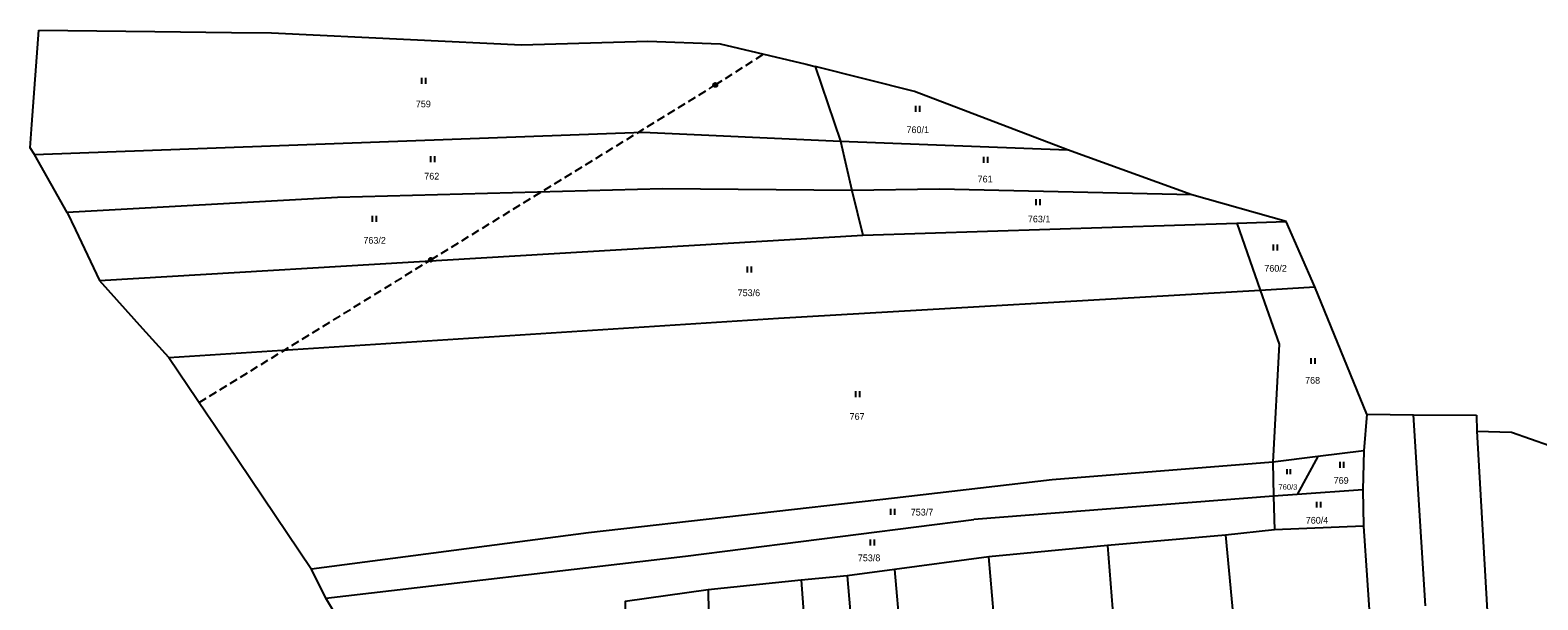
# Model space of a CAD drawing. Extents: x -820420 to -815896, y -1105820 to -1103643.
# Drawn here: x -817269.2 to -816887.9, y -1103786.7 to -1103642.6 of the extents above; entities that cross this region are included whole.
import ezdxf
from ezdxf.enums import TextEntityAlignment as Align

# ---------------------------------------------------------------- set-up
doc = ezdxf.new("R2010")
doc.units = 0
doc.header["$LTSCALE"] = 0.68
doc.linetypes.add('MEDIUM_DASHED', pattern=[4.5, 3, -1.5])
for name, color, linetype, lineweight in [('1', 7, 'Continuous', 25), ('3', 7, 'Continuous', 25), ('6', 7, 'Continuous', 25)]:
    doc.layers.add(name, color=color, linetype=linetype, lineweight=lineweight)
doc.layers.add('2', color=7, linetype='Continuous')

msp = doc.modelspace()

# ---------------------------------------------------------------- linework, layer by layer
at = {"layer": '1'}
for p, q in [((-817268.77, -1103666.4), (-817267.03, -1103642.55)), ((-817267.03, -1103642.55), (-817237.71, -1103642.9)), ((-817237.71, -1103642.9), (-817218.32, -1103643.13)), ((-817218.32, -1103643.13), (-817208.15, -1103643.25)), ((-817208.15, -1103643.25), (-817172.99, -1103644.95)), ((-817172.99, -1103644.95), (-817144.98, -1103646.31)), ((-817144.98, -1103646.31), (-817112.98, -1103645.35)), ((-817112.98, -1103645.35), (-817094.67, -1103645.99)), ((-817094.67, -1103645.99), (-817072.98, -1103651.16)), ((-817072.98, -1103651.16), (-817070.65, -1103651.72)), ((-817070.65, -1103651.72), (-817064.29, -1103670.68)), ((-817045.6, -1103658.05), (-817070.65, -1103651.72)), ((-817006.88, -1103672.86), (-817045.6, -1103658.05)), ((-817269.2, -1103672.33), (-817268.77, -1103666.4)), ((-817268.07, -1103673.99), (-817114.27, -1103668.37)), ((-817114.27, -1103668.37), (-817064.29, -1103670.68)), ((-817268.07, -1103673.99), (-817269.2, -1103672.33)), ((-817259.84, -1103688.71), (-817268.07, -1103673.99)), ((-817064.29, -1103670.68), (-817061.42, -1103683.09)), ((-817064.29, -1103670.68), (-817006.88, -1103672.86)), ((-816975.46, -1103684.22), (-817006.88, -1103672.86)), ((-817191.45, -1103684.88), (-817259.84, -1103688.71)), ((-817109.31, -1103682.73), (-817191.45, -1103684.88)), ((-817061.42, -1103683.09), (-817109.31, -1103682.73)), ((-817039.26, -1103682.79), (-817061.42, -1103683.09)), ((-817061.42, -1103683.09), (-817058.62, -1103694.43)), ((-816975.46, -1103684.22), (-817039.26, -1103682.79)), ((-816951.56, -1103690.98), (-816975.46, -1103684.22)), ((-817259.84, -1103688.71), (-817257.75, -1103693.11)), ((-817257.75, -1103693.11), (-817251.68, -1103705.92)), ((-817058.62, -1103694.43), (-816964.04, -1103691.43)), ((-816964.04, -1103691.43), (-816951.56, -1103690.98)), ((-816964.04, -1103691.43), (-816958.13, -1103708.37)), ((-816944.32, -1103707.51), (-816951.56, -1103690.98)), ((-817251.68, -1103705.92), (-817058.62, -1103694.43)), ((-817240.68, -1103718.11), (-817251.68, -1103705.92)), ((-817079.92, -1103715.44), (-816958.13, -1103708.37)), ((-816958.13, -1103708.37), (-816944.32, -1103707.51)), ((-816958.13, -1103708.37), (-816953.39, -1103721.96)), ((-816931.2, -1103739.74), (-816944.32, -1103707.51)), ((-817234.13, -1103725.37), (-817079.92, -1103715.44)), ((-817234.13, -1103725.37), (-817240.68, -1103718.11)), ((-816953.39, -1103721.96), (-816954.92, -1103751.89)), ((-817234.13, -1103725.37), (-817224.51, -1103739.65)), ((-817224.51, -1103739.65), (-817222.68, -1103742.36)), ((-817222.68, -1103742.36), (-817198.06, -1103778.92)), ((-816931.2, -1103739.74), (-816931.96, -1103748.99)), ((-816931.2, -1103739.74), (-816919.35, -1103739.86)), ((-816919.35, -1103739.86), (-816903.49, -1103739.99)), ((-816916.36, -1103788.24), (-816919.35, -1103739.86)), ((-816903.49, -1103739.99), (-816903.33, -1103744)), ((-816903.33, -1103744), (-816894.6, -1103744.29)), ((-816903.33, -1103744), (-816899.15, -1103817.25)), ((-816894.6, -1103744.29), (-816885, -1103747.66)), ((-816943.57, -1103750.43), (-816954.92, -1103751.89)), ((-816943.57, -1103750.43), (-816948.77, -1103760.03)), ((-816931.96, -1103748.99), (-816943.57, -1103750.43)), ((-816931.96, -1103748.99), (-816932.2, -1103758.85)), ((-816954.92, -1103751.89), (-817010.75, -1103756.36)), ((-816954.92, -1103751.89), (-816954.81, -1103760.47)), ((-817010.75, -1103756.36), (-817050.59, -1103760.95)), ((-817050.59, -1103760.95), (-817128.03, -1103769.75)), ((-816954.81, -1103760.47), (-817030.57, -1103766.4)), ((-816948.77, -1103760.03), (-816954.81, -1103760.47)), ((-816954.81, -1103760.47), (-816954.55, -1103768.95)), ((-816932.2, -1103758.85), (-816948.77, -1103760.03)), ((-816932.2, -1103758.85), (-816932, -1103768.09)), ((-817128.03, -1103769.75), (-817198.06, -1103778.92)), ((-817103.47, -1103775.6), (-817030.57, -1103766.4)), ((-816954.55, -1103768.95), (-816966.95, -1103770.3)), ((-816932, -1103768.09), (-816954.55, -1103768.95)), ((-816932, -1103768.09), (-816928.71, -1103818.04)), ((-816996.77, -1103772.95), (-817026.75, -1103775.77)), ((-816966.95, -1103770.3), (-816996.77, -1103772.95)), ((-816996.77, -1103772.95), (-816989.84, -1103859.69)), ((-816966.95, -1103770.3), (-816961.26, -1103829.11)), ((-817194.45, -1103786.24), (-817103.47, -1103775.6)), ((-817026.75, -1103775.77), (-817050.62, -1103778.98)), ((-817021.9, -1103833.31), (-817026.75, -1103775.77)), ((-817194.45, -1103786.24), (-817198.06, -1103778.92)), ((-817062.57, -1103780.61), (-817074.21, -1103781.74)), ((-817050.62, -1103778.98), (-817062.57, -1103780.61)), ((-817062.57, -1103780.61), (-817057.01, -1103847.39)), ((-817050.62, -1103778.98), (-817044.86, -1103844.47)), ((-817074.21, -1103781.74), (-817097.76, -1103784.19)), ((-817097.76, -1103784.19), (-817096.89, -1103845.62)), ((-817074.21, -1103781.74), (-817069.56, -1103847.4)), ((-817188.41, -1103796.2), (-817194.45, -1103786.24))]:
    msp.add_line(p, q, dxfattribs=at)
msp.add_lwpolyline([(-817097.76, -1103784.19), (-817118.7, -1103787.15), (-817117.52, -1103841.57)], dxfattribs=at)
at = {"layer": '3'}
for p, q in [((-817170.181, -1103656.11), (-817170.181, -1103654.61)), ((-817169.18, -1103656.11), (-817169.18, -1103654.61)), ((-817045.251, -1103663.23), (-817045.251, -1103661.73)), ((-817044.25, -1103663.23), (-817044.25, -1103661.73)), ((-817167.851, -1103675.93), (-817167.851, -1103674.43)), ((-817166.85, -1103675.93), (-817166.85, -1103674.43)), ((-817028.031, -1103676.1), (-817028.031, -1103674.6)), ((-817027.03, -1103676.1), (-817027.03, -1103674.6)), ((-817014.761, -1103686.8), (-817014.761, -1103685.3)), ((-817013.76, -1103686.8), (-817013.76, -1103685.3)), ((-817182.601, -1103691.01), (-817182.601, -1103689.51)), ((-817181.6, -1103691.01), (-817181.6, -1103689.51)), ((-816954.771, -1103698.29), (-816954.771, -1103696.79)), ((-816953.77, -1103698.29), (-816953.77, -1103696.79)), ((-817087.771, -1103703.88), (-817087.771, -1103702.38)), ((-817086.77, -1103703.88), (-817086.77, -1103702.38)), ((-816945.271, -1103727.01), (-816945.271, -1103725.51)), ((-816944.27, -1103727.01), (-816944.27, -1103725.51)), ((-817060.401, -1103735.42), (-817060.401, -1103733.92)), ((-817059.4, -1103735.42), (-817059.4, -1103733.92)), ((-816951.329, -1103754.87), (-816951.329, -1103753.64)), ((-816950.508, -1103754.87), (-816950.508, -1103753.64)), ((-816937.961, -1103753.28), (-816937.961, -1103751.78)), ((-816936.96, -1103753.28), (-816936.96, -1103751.78)), ((-816943.841, -1103763.36), (-816943.841, -1103761.86)), ((-816942.84, -1103763.36), (-816942.84, -1103761.86)), ((-817051.541, -1103765.16), (-817051.541, -1103763.66)), ((-817050.54, -1103765.16), (-817050.54, -1103763.66)), ((-817056.721, -1103772.95), (-817056.721, -1103771.45)), ((-817055.72, -1103772.95), (-817055.72, -1103771.45))]:
    msp.add_line(p, q, dxfattribs=at)
at = {"layer": '6', "linetype": 'MEDIUM_DASHED'}
for p, q in [((-817095.94, -1103656.42), (-817083.75, -1103648.6)), ((-817167.87, -1103700.65), (-817095.94, -1103656.42)), ((-817226.43, -1103736.77), (-817167.87, -1103700.65))]:
    msp.add_line(p, q, dxfattribs=at)
at = {"layer": '6'}
for centre, radius in [((-817095.9434, -1103656.4199), 0.5), ((-817095.9434, -1103656.4199), 0.4), ((-817095.9434, -1103656.4199), 0.3), ((-817095.9434, -1103656.4199), 0.2), ((-817095.9434, -1103656.4199), 0.1), ((-817167.8734, -1103700.6499), 0.5), ((-817167.8734, -1103700.6499), 0.4), ((-817167.8734, -1103700.6499), 0.3), ((-817167.8734, -1103700.6499), 0.2), ((-817167.8734, -1103700.6499), 0.1)]:
    msp.add_circle(centre, radius, dxfattribs=at)

# ---------------------------------------------------------------- texts
at = {"layer": '2'}
for s, height, p in [('759', 1.7, (-817169.779, -1103662.075)), ('760/1', 1.7, (-817044.74, -1103668.605)), ('762', 1.7, (-817167.639, -1103680.345)), ('761', 1.7, (-817027.709, -1103681.085)), ('763/1', 1.7, (-817014.05, -1103691.185)), ('763/2', 1.7, (-817182.09, -1103696.585)), ('760/2', 1.7, (-816954.26, -1103703.665)), ('753/6', 1.7, (-817087.45, -1103709.855)), ('768', 1.7, (-816944.899, -1103732.005)), ('767', 1.7, (-817060.079, -1103741.145)), ('760/3', 1.386, (-816951.14, -1103758.836)), ('769', 1.7, (-816937.669, -1103757.335)), ('753/7', 1.7, (-817043.67, -1103765.355)), ('760/4', 1.7, (-816943.78, -1103767.405)), ('753/8', 1.7, (-817057.05, -1103776.915))]:
    msp.add_text(s, height=height, dxfattribs=at).set_placement(p, align=Align.CENTER)

doc.saveas('drawing.dxf')
